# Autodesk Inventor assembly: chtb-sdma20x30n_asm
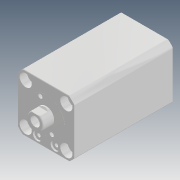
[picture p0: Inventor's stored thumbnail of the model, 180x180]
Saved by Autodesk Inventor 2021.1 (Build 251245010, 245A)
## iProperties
Created: 2018-05
Part Number: chtb-sdma20x30n_asm
Description: STEP AP214
Document SubType Name: Assembly
Designer: user
Title: chtb-sdma20x30n_asm.STEP
Revision Number: ÈÎºÎ
Sending System: SolidWorks 2016
Preprocessor: SwSTEP 2.0
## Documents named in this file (5)
- D:\Vault_2016\Projekty\Clamptek\Hydraulic\CHTB\CHTB-20\Inventor\CHTB-SDMA20x30N\chtb-sdma20x30n_asm.iam
- D:\Vault_2016\Projekty\Clamptek\Hydraulic\CHTB\CHTB-20\Inventor\CHTB-SDMA20x30N\CHTB-SDMA20X30NBT.ipt
- D:\Vault_2016\Projekty\Clamptek\Hydraulic\CHTB\CHTB-20\Inventor\CHTB-SDMA20x30N\CHTB-SDMA20X30NHSG.ipt
- D:\Vault_2016\Projekty\Clamptek\Hydraulic\CHTB\CHTB-20\Inventor\CHTB-SDMA20x30N\QG_3.ipt
- D:\Vault_2016\Projekty\Clamptek\Hydraulic\CHTB\CHTB-20\Inventor\CHTB-SDMA20x30N\socket set screw flat point_iso_ISO 4026 - M5 x 5-N.ipt
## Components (5 placed, 5 different names)
1. CHTB-SDMA20X30NBT_1
2. CHTB-SDMA20X30NHSG_2
3. QG_3_3
4. socket set screw flat point_iso_ISO 4026 - M5 x 5-N_4
5. socket set screw flat point_iso_ISO 4026 - M5 x 5-N_5
